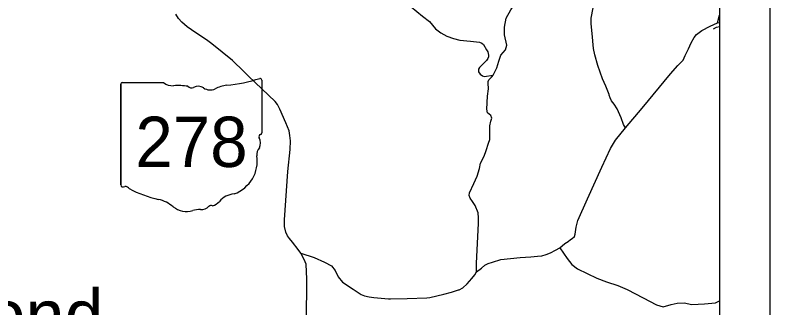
# Model space of a CAD drawing. Extents: x -22 to 431, y -18 to 160.
# Drawn here: x -16.478 to -14.978, y 26.065 to 26.647 of the extents above; entities that cross this region are included whole.
import ezdxf

# ---------------------------------------------------------------- set-up
doc = ezdxf.new("R2010")
doc.units = 0
for name, color, linetype in [('GM_X_Adjacent_County', 7, 'Continuous'), ('GM_X_Adjacent_County_Text', 7, 'Continuous'), ('GM_X_Airport_Location_Class_2', 7, 'Continuous'), ('GM_X_County_Road', 7, 'Continuous'), ('GM_X_County_ROW', 7, 'Continuous'), ('GM_X_Minor_River', 7, 'Continuous'), ('GM_X_Minor_River_Text', 7, 'Continuous'), ('GM_X_Section', 7, 'Continuous')]:
    doc.layers.add(name, color=color, linetype=linetype)

msp = doc.modelspace()

# ---------------------------------------------------------------- linework, layer by layer
at = {"layer": 'GM_X_Adjacent_County_Text'}
msp.add_lwpolyline([(-15.9104, 26.1741), (-15.8838, 26.1651), (-15.8635, 26.1557), (-15.8494, 26.1484), (-15.8421, 26.1396), (-15.836, 26.1265), (-15.8272, 26.1161), (-15.8062, 26.1024), (-15.7904, 26.0919), (-15.7834, 26.0887), (-15.7745, 26.0869), (-15.7651, 26.0857), (-15.7358, 26.0829), (-15.7323, 26.083), (-15.6989, 26.0839), (-15.6594, 26.0852), (-15.654, 26.0854), (-15.6261, 26.0922), (-15.6107, 26.096), (-15.5969, 26.1006), (-15.5953, 26.1012), (-15.5881, 26.1051), (-15.5794, 26.1126), (-15.5702, 26.1232), (-15.5646, 26.1305), (-15.561, 26.1368), (-15.5513, 26.1441), (-15.5442, 26.1499), (-15.5376, 26.153), (-15.5293, 26.1562), (-15.5123, 26.1609), (-15.4743, 26.1651), (-15.4529, 26.1667), (-15.4394, 26.1678), (-15.4309, 26.1683), (-15.4224, 26.171), (-15.4137, 26.1746), (-15.4042, 26.1798), (-15.3953, 26.1847), (-15.3854, 26.193), (-15.3784, 26.1972), (-15.3738, 26.2011), (-15.3706, 26.203), (-15.3664, 26.2069), (-15.365, 26.2115), (-15.3629, 26.2252), (-15.3593, 26.2389), (-15.3404, 26.2818), (-15.3116, 26.345), (-15.2943, 26.3821), (-15.2847, 26.3987), (-15.2648, 26.4233), (-15.2318, 26.4624), (-15.1755, 26.5305), (-15.1606, 26.5467), (-15.1502, 26.5572), (-15.1459, 26.5666), (-15.1393, 26.5798), (-15.134, 26.5918), (-15.1283, 26.6023), (-15.1238, 26.6084), (-15.1131, 26.6167), (-15.0962, 26.6253), (-15.0821, 26.6318), (-15.0776, 26.647)], dxfattribs=at)
at = {"layer": 'GM_X_Airport_Location_Class_2'}
for p, q in [((-16.2682, 26.5096), (-16.2682, 26.3094)), ((-16.2682, 26.3094), (-16.2682, 26.5096)), ((-16.2682, 26.3094), (-16.2682, 26.5096)), ((-16.2654, 26.513), (-16.1834, 26.513)), ((-15.9881, 26.518), (-15.9881, 26.4133)), ((-15.9881, 26.4133), (-15.9881, 26.4133))]:
    msp.add_line(p, q, dxfattribs=at)
for centre, major_axis, start_param, end_param in [((-16.0879, 26.7858), (0.2971, 0), 4.814394, 5.042369), ((-15.9912, 26.5184), (0.00312, 0), 6.141152, 7.989035), ((-16.265, 26.51), (0.00325, 0), 1.712693, 3.28349), ((-16.1639, 26.5362), (0.0315, 0), 4.042523, 4.731795), ((-16.1534, 26.4007), (0.113, 0), 1.404758, 1.657858), ((-16.1278, 26.511), (0.00908, 0), 3.836095, 5.185415), ((-16.1144, 26.4879), (0.0189, 0), 0.950623, 2.079405), ((-16.05, 26.4519), (0.0598, 0), 1.699011, 2.107814), ((-16.0901, 26.5196), (0.0227, 0), 4.081561, 5.145723), ((-15.9888, 26.4056), (0.00483, 0), 1.883978, 3.671073), ((-16.0195, 26.3924), (0.029, 0), 5.934695, 6.695948), ((-15.9914, 26.4129), (0.00334, 0), 5.05454, 6.418171), ((-15.9769, 26.3695), (0.0211, 0), 2.387724, 3.262537), ((-16.0712, 26.3562), (0.0743, 0), 5.101752, 6.440018), ((-16.265, 26.309), (0.00327, 0), 3.00124, 4.508301), ((-16.2645, 26.3295), (0.025, 0), 4.665946, 4.897461), ((-16.2594, 26.2979), (0.00901, 0), 0.519207, 1.627899), ((-16.1456, 26.4777), (0.2145, 0), 4.195997, 4.488961), ((-16.2096, 26.2195), (0.0671, 0), 0.823519, 1.323587), ((-16.0399, 26.2533), (0.0407, 0), 1.647645, 2.488434), ((-16.137, 26.2969), (0.0426, 0), 4.026481, 4.996735), ((-16.1092, 26.2819), (0.0227, 0), 4.691044, 5.507374), ((-16.0887, 26.2625), (0.00639, 0), 1.147584, 2.315152), ((-16.0914, 26.2901), (0.024, 0), 4.937069, 5.64225), ((-16.1124, 26.2277), (0.035, 0), 1.495662, 1.94098)]:
    msp.add_ellipse(centre, major_axis=major_axis, ratio=0.941176, start_param=start_param, end_param=end_param, dxfattribs=at)
at = {"layer": 'GM_X_County_Road'}
for points in [[(-15.515, 26.5598), (-15.5145, 26.5612), (-15.5123, 26.5673), (-15.5034, 26.5778), (-15.5007, 26.5874), (-15.5053, 26.6078), (-15.5053, 26.623), (-15.502, 26.6409), (-15.4924, 26.6579), (-15.4831, 26.6724), (-15.4818, 26.6882), (-15.4771, 26.7031), (-15.4725, 26.7249), (-15.4621, 26.7389), (-15.4582, 26.7667), (-15.4526, 26.7863)], [(-15.691, 26.6634), (-15.6685, 26.6448), (-15.6545, 26.6347), (-15.6427, 26.6201), (-15.6322, 26.6119), (-15.6202, 26.6055), (-15.6067, 26.6004), (-15.5938, 26.5976), (-15.573, 26.5953), (-15.5553, 26.593), (-15.5506, 26.5915), (-15.547, 26.5884), (-15.5412, 26.5784), (-15.5386, 26.5743), (-15.5371, 26.5676), (-15.5372, 26.5642), (-15.5383, 26.5609), (-15.5414, 26.557), (-15.5516, 26.5464), (-15.5552, 26.543), (-15.5572, 26.5395), (-15.5568, 26.5346), (-15.5538, 26.5295), (-15.5492, 26.5261), (-15.5454, 26.525), (-15.528, 26.5279)]]:
    msp.add_lwpolyline(points, dxfattribs=at)
at = {"layer": 'GM_X_County_ROW'}
msp.add_lwpolyline([(-15.8989, 26.0381), (-15.8984, 26.1218), (-15.8996, 26.1521), (-15.9035, 26.1615), (-15.9104, 26.1741), (-15.9155, 26.181), (-15.9271, 26.1956), (-15.9331, 26.2031), (-15.937, 26.2084), (-15.9402, 26.2155), (-15.9425, 26.2267), (-15.9426, 26.2403), (-15.9359, 26.3359), (-15.9314, 26.3796), (-15.9306, 26.3974), (-15.9318, 26.4079), (-15.9336, 26.4169), (-15.9398, 26.4328), (-15.9523, 26.46), (-15.9547, 26.4653), (-15.9568, 26.4691), (-15.9615, 26.4752), (-16.014, 26.5257), (-16.0235, 26.5352), (-16.0463, 26.557), (-16.0873, 26.5898), (-16.0979, 26.598), (-16.1191, 26.612), (-16.1362, 26.6237), (-16.1466, 26.6333), (-16.1532, 26.6406), (-16.1588, 26.6492)], dxfattribs=at)
at = {"layer": 'GM_X_Minor_River'}
msp.add_lwpolyline([(-15.09, 26.6199), (-15.0835, 26.6229), (-15.0776, 26.6244)], dxfattribs=at)
at = {"layer": 'GM_X_Minor_River_Text'}
msp.add_line((-15.0821, 26.6318), (-15.0776, 26.6322), dxfattribs=at)
for points in [[(-15.2975, 26.4894), (-15.2984, 26.4923), (-15.3039, 26.5061), (-15.3102, 26.5206), (-15.3149, 26.5336), (-15.3198, 26.5468), (-15.3258, 26.5684), (-15.3283, 26.5809), (-15.3308, 26.6107), (-15.333, 26.63), (-15.3333, 26.6412), (-15.3293, 26.6613)], [(-15.561, 26.1368), (-15.5613, 26.154), (-15.5573, 26.2327), (-15.5567, 26.2441), (-15.5578, 26.2537), (-15.5639, 26.2688), (-15.5689, 26.2767), (-15.5738, 26.2833), (-15.5754, 26.2882), (-15.5751, 26.2941), (-15.566, 26.3126), (-15.5594, 26.3272), (-15.5551, 26.342), (-15.5528, 26.3527), (-15.5456, 26.3664), (-15.5416, 26.3779), (-15.5369, 26.3924), (-15.5347, 26.3996), (-15.5347, 26.4117), (-15.5345, 26.4267), (-15.5324, 26.4364), (-15.5306, 26.4423), (-15.5324, 26.4475), (-15.5389, 26.4527), (-15.5407, 26.4602), (-15.539, 26.4857), (-15.5369, 26.5003), (-15.5378, 26.5115), (-15.5375, 26.5151), (-15.5364, 26.5182), (-15.5305, 26.5243), (-15.528, 26.5279), (-15.5203, 26.5425), (-15.5165, 26.5555), (-15.515, 26.5598)], [(-15.2648, 26.4233), (-15.269, 26.4298), (-15.2736, 26.4429), (-15.2816, 26.461), (-15.2871, 26.47), (-15.2923, 26.477), (-15.2954, 26.4826), (-15.2971, 26.4881), (-15.2975, 26.4894)], [(-15.3953, 26.1847), (-15.3806, 26.1629), (-15.3715, 26.151), (-15.3602, 26.143), (-15.3217, 26.1242), (-15.3024, 26.1168), (-15.2797, 26.1093), (-15.2614, 26.1018), (-15.2295, 26.085), (-15.2034, 26.0709), (-15.1899, 26.0673), (-15.174, 26.0716), (-15.1619, 26.0745), (-15.1481, 26.0752), (-15.1325, 26.072), (-15.1073, 26.0729), (-15.0857, 26.0753), (-15.0776, 26.0792)]]:
    msp.add_lwpolyline(points, dxfattribs=at)
at = {"layer": 'GM_X_Section'}
for p, q in [((-14.9776, 29.1642), (-14.9776, 22.1642)), ((-15.0776, 29.0642), (-15.0776, 22.2642)), ((-15.0776, 29.0642), (-15.0776, 22.2642))]:
    msp.add_line(p, q, dxfattribs=at)

# ---------------------------------------------------------------- texts
at = {"layer": 'GM_X_Adjacent_County'}
msp.add_text('Red Diamond', height=0.104167, rotation=0, dxfattribs=at).set_placement((-17.1543, 25.9976))
at = {"layer": 'GM_X_Airport_Location_Class_2'}
msp.add_text('278', height=0.1, dxfattribs=at).set_placement((-16.2392, 26.3452))

doc.saveas('drawing.dxf')
